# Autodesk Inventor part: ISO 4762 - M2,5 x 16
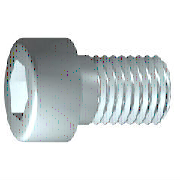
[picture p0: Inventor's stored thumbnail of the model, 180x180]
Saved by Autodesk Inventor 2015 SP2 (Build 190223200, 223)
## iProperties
Created: 2012-02
Part Number: ISO 4762 - M2,5 x 16
Material: Edelstahl, 440C
Description: Innensechskantschraube
Document SubType Name: Modeling
Standard: ISO 4762
Designer: Hübner
Standard Revision: 1998
Standards Organization: DIN
Language: de-DE
Size Designation: M2,5 x 16
Categories: <MemberInstance><Categories><Category DisplayName="Verbindungselemente" InternalName="e4da775c-781d-43d5-af7c-5136215cf5a6" Mnemonic="FSTN"><Category DisplayNam
Density: 7.75 g/cm^3
Appearance: Halbpoliert
IsCustomPart: 0
Author: Hübner
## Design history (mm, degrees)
sketch "Skizze1"
  geometry: L1 (-0.733, 0)-(16, 0); L2 (16, 0)-(16, 1.25); L3 (16, 1.25)-(1.125, 1.25); L4 (1.125, 1.25)-(0.849, 1.25); L5 (0.849, 1.25)-(0, 1.25); L6 (0, 1.25)-(0, 2.25); L7 (0, 2.25)-(-2.5, 2.25); L8 (-2.5, 2.25)-(-2.5, 1.155); L9 (-2.5, 1.155)-(-1.4, 1.155); L10 (-1.4, 1.155)-(-0.733, 0); L11 (-6.2, 0)-(19.7, 0) reference; L12 (0, -0.45)-(0, 2.7) reference; L13 (1.125, 1.25)-(0, 1.25)
  constraints: 22 end point, 6 parallel, 2 collinear, 2 perpendicular, 1 horizontal, 1 point on line
  dimensions: "d1" = 14.875 distance from line of L3.end L2 (= GEL); "d2" = 0.27615 distance of L4.end L3.end (computed from GAL); "d3" = 2.5 distance between parallel lines of L8 L6 (= KOH); "d4" = 1.1 distance of L8.end L9.end (= INTI); "d5" = 60 deg angle of L10 L1; "d6" = 2.5 diameter of L3 L1 (= GD); "d7" = 2.5 diameter of L5 L1 (= BDM); "d8" = 2.3094 diameter of L9 L1 (= 1.1547 x SW); "d9" = 4.5 diameter of L7 L1 (= KOD); "d26" = 16 distance between parallel lines of L12 L2 (= NLG)
revolve "Körper" sketch "Skizze1" stored, may be unused: angle "d10" = 90 deg
sketch "Skizze2"
  geometry: L1 (0, -3.15)-(0, 3.15) reference; L2 (-3.15, 0)-(3.15, 0) reference; L3 (1.155, 0)-(0.577, -1); L4 (0.577, -1)-(-0.577, -1); L5 (-0.577, -1)-(-1.155, 0); L6 (-1.155, 0)-(-0.577, 1); L7 (-0.577, 1)-(0.577, 1); L8 (0.577, 1)-(1.155, 0); 2 further points
  constraints: 12 end point, 1 coincident, 1 horizontal alignment, 1 point on line, 12 other
extrude "Loch" join sketch "Skizze2" stored distance "d11" = 10; taper "d12" = 0 deg
workplane "Work Plane1"
fillet "Fillet2" dims "d30" = 0.1 (= R)
body "Solid1"
fillet "Rundung1" dims "d17" = 0.25 (= RR)
feature "Gewinde" dims "d13" = 14.875 (= GEL), "d14" = 0
chamfer "Fase1" distance "d15" = 0.27605 (= -0.5 x SPD + 0.5 x GD); stored, may be unused: second distance "d16" = 0.27605 (= GUL), angle "d27" = 45 deg
other parameters: "GD" = 2.5 [user parameter; used in 2 equation terms], "NLG" = 16 [user parameter; used in 1 equation term], "GEL" = 14.875 [user parameter; used in 2 equation terms], "KOD" = 4.5 [user parameter; used in 1 equation term], "KOH" = 2.5 [user parameter; used in 1 equation term], "INTI" = 1.1 [user parameter; used in 1 equation term], "GAL" = 0.27605 (= 0.61345 x PTC) [user parameter; used in 1 equation term], "GUL" = 0.27605 (= 0.61345 x PTC) [user parameter; used in 1 equation term], "BDM" = 2.5 (= NND) [user parameter; used in 1 equation term], "SW" = 2 [user parameter; used in 2 equation terms], "RR" = 0.25 [user parameter; used in 1 equation term], "SPD" = 1.94789 (= NND - 1.2269 x PTC) [user parameter; used in 1 equation term], "d19" = 0, "d28" = 0, "d29" = 0, "R" = 0.1 [user parameter; used in 1 equation term], "TOA" = 30 deg [user parameter], "GD1" = 1.94789 (= THREADDIA - 1.2269 x PTC) [user parameter], "THREADDIA" = 2.5 [user parameter; used in 1 equation term], "FAWI" = 45 deg [user parameter], "TPU" = 22.22222 (computed from PTC) [user parameter], "PTC" = 0.45 [user parameter; used in 5 equation terms], "NND" = 2.5 [user parameter; used in 2 equation terms], "E0" = 2.31 (= 1.155 x SW) [user parameter]
